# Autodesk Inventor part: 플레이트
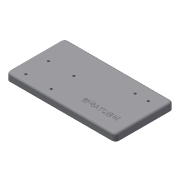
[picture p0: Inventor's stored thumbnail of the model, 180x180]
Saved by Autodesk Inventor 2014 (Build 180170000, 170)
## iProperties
Created: 2018-01
Part Number: 플레이트
Material: Aluminum 6061
Document SubType Name: Modeling
Designer: mduedu
Density: 2.71 g/cm^3
Mass: 319.562 g
Surface Area: 287.617 cm^2
Volume: 117.92 cm^3
Appearance: Default
Author: mduedu
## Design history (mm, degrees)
sketch "스케치1"
  geometry: L1 (75, 40)-(-75, 40); L2 (-75, 40)-(-75, -40); L3 (-75, -40)-(75, -40); L4 (75, -40)-(75, 40); L5 (75, 40)-(-75, -40); L6 (-75, 40)-(75, -40); 1 further point
  constraints: 12 end point, 2 midpoint, 2 parallel, 1 horizontal, 1 perpendicular
  dimensions: "d0" = 150 distance of L3.end L2.end; "d1" = 80 distance of L2.end L1.end
extrude "돌출1" new body sketch "스케치1" distance "d2" = 10; taper "d3" = 0 deg
fillet "모깎기1" dims "d4" = 5
fillet "모깎기2" dims "d5" = 3
sketch "스케치2"
  geometry: L1 (-70, 40)-(70, 40) reference; L2 (-75, -35)-(-75, 35) reference; 5 further points
  constraints: 2 horizontal alignment, 2 vertical alignment
  dimensions: "d6" = 10 distance from line of point (-58, 30) L1; "d7" = 35 distance of point (-23, 30) point (-58, 30); "d8" = 31 distance of point (-58, -1) point (-58, 30); "d9" = 17 distance from line of point (-58, 30) L2
sketch "스케치3"
  geometry: 4 further points
  constraints: 4 other
hole "구멍1" sketch "스케치3" at (-23, 30), (-58, -1), (-23, -1), (-58, 30) diameter "d10" = 3.4; stored, may be unused: countersink angle "d14" = 90 deg, drill point angle "d16" = 0 deg; dims "d11" = 6, "d12" = 6.5, "d13" = 3.4, "d15" = 8
sketch "스케치4"
  geometry: L1 (75, 35)-(75, -35) reference; L2 (70, -40)-(-70, -40) reference; 3 further points
  constraints: 1 horizontal alignment
  dimensions: "d17" = 17 distance from line of point (58, -22) L1; "d18" = 18 distance of point (40, -22) point (58, -22); "d19" = 18 distance from line of point (58, -22) L2
sketch "스케치5"
  geometry: 2 further points
  constraints: 2 other
hole "구멍2" sketch "스케치5" at (40, -22), (58, -22) diameter "d20" = 3.4; stored, may be unused: countersink angle "d24" = 90 deg, drill point angle "d26" = 0 deg; dims "d21" = 6, "d22" = 6.5, "d23" = 3.4, "d25" = 8
sketch "스케치6"
  geometry: L1 (75, -35)-(75, 35) reference; L2 (-70, -40)-(70, -40) reference; 2 further points
  constraints: 1 other
  dimensions: "d27" = 40 distance from line of point (35, -20) L1; "d28" = 20 distance from line of point (35, -20) L2
feature "엠보싱1" sketch "스케치6" dims "d0" = 150, "d29" = 0.5, "d30" = 0
node "솔리드1"
